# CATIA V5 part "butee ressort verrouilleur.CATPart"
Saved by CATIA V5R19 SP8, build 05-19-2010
Part number: butee ressort verrouilleur
Revision: ANY
Definition: UNKNOWN
Nomenclature: butee ressort verrouilleur
Source: Unknown
Bounding box of the stored display mesh (mm): x -5 to 5, y -2 to 7, z -3.5 to 6
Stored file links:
  D:\Documents\1_Travail\1 - ac-limoges.fr\ac-limoges.fr\Emmanuel Maynard - STI2D_Turgot\2 -2I2D\2_SEQUENCE_Serrure_Biométrique\5-Spé_ITEC\Serrure_Bio_Eleve\butee ressort verrouilleur.CATPart
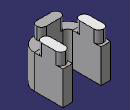
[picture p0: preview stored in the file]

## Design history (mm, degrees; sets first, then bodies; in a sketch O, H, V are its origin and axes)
Body1 "Extru.-Mince2" (main body)
  Solid1: solid without history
